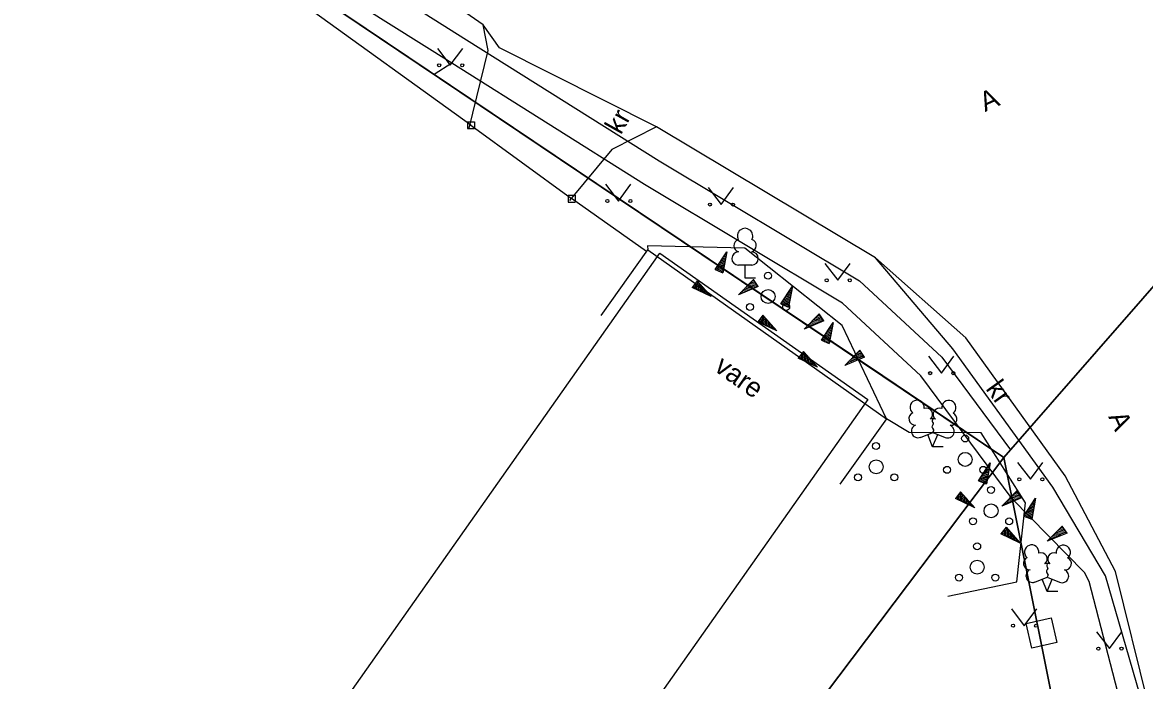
# Model space of a CAD drawing. Extents: x 554947 to 555436, y 6564938 to 6565792.
# Drawn here: x 555307.9 to 555348.19, y 6565504.44 to 6565528.08 of the extents above; entities that cross this region are included whole.
import ezdxf

# ---------------------------------------------------------------- set-up
doc = ezdxf.new("R2010")
doc.units = 0
for name, color, linetype in [('AED', 7, 'Continuous'), ('HALJASTUS', 7, 'Continuous'), ('HOONE', 7, 'Continuous'), ('Hoone Vare', 7, 'Continuous'), ('KASUTUSALA', 7, 'Continuous'), ('PIIR', 7, 'Continuous'), ('PR_SIDE', 7, 'Continuous'), ('PUU', 7, 'Continuous'), ('RELJEEF', 7, 'Continuous'), ('TEE', 7, 'Continuous')]:
    doc.layers.add(name, color=color, linetype=linetype)

msp = doc.modelspace()

# ---------------------------------------------------------------- linework, layer by layer
at = {"layer": 'AED'}
for p, q in [((555323.878, 6565524.515), (555323.878, 6565524.265)), ((555323.878, 6565524.515), (555324.128, 6565524.515)), ((555323.878, 6565524.265), (555324.128, 6565524.265)), ((555324.003, 6565524.39), (555327.619, 6565521.751)), ((555324.128, 6565524.515), (555324.128, 6565524.265)), ((555327.494, 6565521.876), (555327.494, 6565521.626)), ((555327.494, 6565521.876), (555327.744, 6565521.876)), ((555327.744, 6565521.876), (555327.744, 6565521.626)), ((555327.494, 6565521.626), (555327.744, 6565521.626)), ((555330.309, 6565519.858), (555327.619, 6565521.751))]:
    msp.add_line(p, q, dxfattribs=at)
msp.add_lwpolyline([(555324.003, 6565524.39), (555318.054, 6565528.671), (555308.195, 6565535.788)], dxfattribs=at)
msp.add_lwpolyline([(555344.829, 6565506.702), (555345.035, 6565505.809), (555344.14, 6565505.602), (555343.934, 6565506.496)], close=True, dxfattribs=at)
at = {"layer": 'HALJASTUS'}
for p, q in [((555322.798, 6565527.146), (555323.262, 6565526.539)), ((555323.262, 6565526.539), (555323.707, 6565527.146)), ((555328.838, 6565522.273), (555329.302, 6565521.666)), ((555329.302, 6565521.666), (555329.747, 6565522.273)), ((555332.519, 6565522.146), (555332.983, 6565521.539)), ((555332.983, 6565521.539), (555333.428, 6565522.146)), ((555336.713, 6565519.424), (555337.177, 6565518.818)), ((555337.177, 6565518.818), (555337.622, 6565519.424)), ((555340.429, 6565516.091), (555340.892, 6565515.484)), ((555340.892, 6565515.484), (555341.338, 6565516.091)), ((555343.628, 6565512.278), (555344.091, 6565511.672)), ((555344.091, 6565511.672), (555344.537, 6565512.278)), ((555343.405, 6565507.019), (555343.868, 6565506.412)), ((555343.868, 6565506.412), (555344.314, 6565507.019)), ((555346.467, 6565506.198), (555346.931, 6565505.591)), ((555346.931, 6565505.591), (555347.376, 6565506.198))]:
    msp.add_line(p, q, dxfattribs=at)
msp.add_lwpolyline([(555341.125, 6565507.476), (555343.606, 6565507.989), (555343.913, 6565510.824), (555342.324, 6565513.336), (555339.74, 6565513.358), (555338.917, 6565513.849)], dxfattribs=at)
for centre in [(555322.861, 6565526.539), (555323.69, 6565526.539), (555328.9, 6565521.666), (555329.729, 6565521.666), (555332.582, 6565521.539), (555333.411, 6565521.539), (555336.776, 6565518.818), (555337.604, 6565518.818), (555340.491, 6565515.484), (555341.32, 6565515.484), (555343.69, 6565511.672), (555344.519, 6565511.672), (555343.467, 6565506.412), (555344.296, 6565506.412), (555346.53, 6565505.591), (555347.359, 6565505.591)]:
    msp.add_circle(centre, 0.055, dxfattribs=at)
at = {"layer": 'HOONE'}
msp.add_lwpolyline([(555328.683, 6565517.559), (555330.348, 6565519.912), (555338.917, 6565513.849), (555337.251, 6565511.495)], dxfattribs=at)
at = {"layer": 'Hoone Vare'}
msp.add_lwpolyline([(555316.008, 6565482.956), (555308.549, 6565488.207), (555330.789, 6565519.787), (555338.249, 6565514.537)], close=True, dxfattribs=at)
at = {"layer": 'KASUTUSALA'}
msp.add_lwpolyline([(555304.515, 6565541.003), (555310.279, 6565536.49), (555319.603, 6565530.14), (555323.849, 6565527.459), (555330.764, 6565523.11), (555337.948, 6565518.804), (555340.906, 6565516.057), (555343.377, 6565512.73), (555343.14, 6565512.46), (555338.794, 6565515.382), (555330.79, 6565520.761), (555305.197, 6565537.964)], dxfattribs=at)
at = {"layer": 'PIIR'}
for points in [[(555393.069, 6565560.972), (555353.12, 6565523.87), (555343.14, 6565512.46), (555302.6, 6565539.71), (555242.37, 6565583.94), (555179.42, 6565586.32), (555138.98, 6565580.6), (555121.18, 6565602.26), (555116.17, 6565610.5), (555109.96, 6565624.83), (555093.56, 6565628.47), (555079.04, 6565618.4), (555074.13, 6565607.82), (555075.34, 6565593.24), (555091.74, 6565551.94), (555171.91, 6565394.64), (555191.35, 6565341.19), (555195.08, 6565294.61), (555195.28, 6565271.63), (555191.64, 6565237.48)], [(555393.069, 6565443.872), (555367.06, 6565449.68), (555351.96, 6565468.55), (555343.14, 6565512.46), (555353.12, 6565523.87), (555358.8, 6565482.45), (555368.05, 6565461.11), (555393.069, 6565454.923)]]:
    msp.add_lwpolyline(points, dxfattribs=at)
for points in [[(555153.01, 6565448.47), (555161.15, 6565451.45), (555173.66, 6565456.03), (555207.29, 6565506.14), (555287.77, 6565518.56), (555302.6, 6565539.71), (555343.14, 6565512.46), (555319.44, 6565481.04), (555323.07, 6565461.26), (555312.9, 6565433.84), (555316.84, 6565372.52), (555318.72, 6565342.57), (555320.51, 6565314.61), (555303.13, 6565302.54), (555208.78, 6565303.3), (555205.15, 6565297.11), (555200.72, 6565310.3), (555206.9, 6565339.44), (555221.23, 6565376.06), (555216.83, 6565392.35), (555207.22, 6565406.57)], [(555319.44, 6565481.04), (555343.14, 6565512.46), (555351.96, 6565468.55), (555367.06, 6565449.68), (555367.76, 6565374.28), (555361.76, 6565374.07), (555316.84, 6565372.52), (555312.9, 6565433.84), (555323.07, 6565461.26)]]:
    msp.add_lwpolyline(points, close=True, dxfattribs=at)
at = {"layer": 'PR_SIDE'}
for points in [[(555393.069, 6565447.47), (555392.755, 6565447.532), (555372.326, 6565450.448), (555366.015, 6565452.342), (555363.26, 6565453.626), (555360.292, 6565456.785), (555356.82, 6565461.856), (555353.746, 6565469.93), (555350.28, 6565487.806), (555348.596, 6565498.754), (555346.199, 6565508), (555346.027, 6565508.326), (555343.44, 6565510.968), (555340.158, 6565515.387), (555337.344, 6565518), (555330.24, 6565522.258), (555323.316, 6565526.613), (555319.055, 6565529.304), (555309.687, 6565535.684), (555303.916, 6565540.202)], [(555323.316, 6565526.613), (555322.686, 6565526.209)]]:
    msp.add_lwpolyline(points, dxfattribs=at)
at = {"layer": 'PUU'}
for p, q in [((555334.085, 6565519.365), (555333.605, 6565519.365)), ((555333.845, 6565518.89), (555333.845, 6565519.365)), ((555334.225, 6565518.89), (555333.845, 6565518.89)), ((555340.14, 6565513.177), (555340.585, 6565513.352)), ((555340.585, 6565513.352), (555341.025, 6565513.172)), ((555340.58, 6565512.842), (555340.405, 6565513.282)), ((555340.58, 6565512.842), (555340.76, 6565513.282)), ((555340.96, 6565512.842), (555340.58, 6565512.842)), ((555344.251, 6565507.981), (555344.696, 6565508.156)), ((555344.691, 6565507.646), (555344.516, 6565508.086)), ((555344.691, 6565507.646), (555344.871, 6565508.086)), ((555344.696, 6565508.156), (555345.136, 6565507.976)), ((555345.071, 6565507.646), (555344.691, 6565507.646))]:
    msp.add_line(p, q, dxfattribs=at)
for points in [[(555340.585, 6565513.847), (555340.565, 6565513.772), (555340.565, 6565513.752), (555340.575, 6565513.722), (555340.595, 6565513.687), (555340.6, 6565513.667), (555340.585, 6565513.632), (555340.56, 6565513.582), (555340.555, 6565513.557), (555340.56, 6565513.542), (555340.57, 6565513.512), (555340.605, 6565513.452), (555340.61, 6565513.432), (555340.605, 6565513.412), (555340.59, 6565513.377), (555340.585, 6565513.352)], [(555344.696, 6565508.651), (555344.676, 6565508.576), (555344.676, 6565508.556), (555344.686, 6565508.526), (555344.706, 6565508.491), (555344.711, 6565508.471), (555344.696, 6565508.436), (555344.671, 6565508.386), (555344.666, 6565508.361), (555344.671, 6565508.346), (555344.681, 6565508.316), (555344.716, 6565508.256), (555344.721, 6565508.236), (555344.716, 6565508.216), (555344.701, 6565508.181), (555344.696, 6565508.156)]]:
    msp.add_lwpolyline(points, dxfattribs=at)
for centre, radius in [((555334.67, 6565518.984), 0.125), ((555334.67, 6565518.234), 0.25), ((555334.02, 6565517.859), 0.125), ((555335.32, 6565517.859), 0.125), ((555338.55, 6565512.867), 0.125), ((555341.746, 6565513.137), 0.125), ((555341.746, 6565512.387), 0.25), ((555338.55, 6565512.117), 0.25), ((555341.096, 6565512.012), 0.125), ((555342.396, 6565512.012), 0.125), ((555337.9, 6565511.742), 0.125), ((555339.2, 6565511.742), 0.125), ((555342.676, 6565511.289), 0.125), ((555342.676, 6565510.539), 0.25), ((555342.026, 6565510.164), 0.125), ((555343.326, 6565510.164), 0.125), ((555342.177, 6565509.265), 0.125), ((555342.177, 6565508.515), 0.25), ((555341.527, 6565508.14), 0.125), ((555342.827, 6565508.14), 0.125)]:
    msp.add_circle(centre, radius, dxfattribs=at)
for centre, radius, start, end in [((555333.845, 6565520.41), 0.277, 332.5799, 207.4201), ((555333.675, 6565520.062), 0.233, 109.0217, 253.1415), ((555334.015, 6565520.062), 0.233, 286.8508, 70.9859), ((555333.607, 6565519.602), 0.238, 90.0016, 269.3953), ((555334.082, 6565519.602), 0.238, 270.6047, 89.9984), ((555340.023, 6565514.256), 0.256, 111.5027, 232.5173), ((555340.023, 6565514.256), 0.256, 350.4856, 111.5002), ((555340.358, 6565514.006), 0.224, 308.5041, 111.5725), ((555340.821, 6565514.001), 0.225, 67.7016, 230.5126), ((555341.159, 6565514.248), 0.256, 67.6168, 188.6314), ((555341.159, 6565514.248), 0.256, 306.5997, 67.6143), ((555339.949, 6565513.845), 0.224, 111.4304, 274.4987), ((555340.584, 6565513.609), 0.237, 66.7655, 111.5015), ((555341.227, 6565513.835), 0.224, 264.6183, 67.6866), ((555340.054, 6565513.401), 0.237, 111.5014, 291.5004), ((555341.115, 6565513.392), 0.237, 247.6166, 67.6155), ((555344.134, 6565509.06), 0.256, 111.5027, 232.5173), ((555344.134, 6565509.06), 0.256, 350.4856, 111.5002), ((555345.27, 6565509.051), 0.256, 67.6168, 188.6314), ((555345.27, 6565509.051), 0.256, 306.5997, 67.6143), ((555344.468, 6565508.81), 0.224, 308.5041, 111.5725), ((555344.932, 6565508.805), 0.225, 67.7016, 230.5126), ((555344.06, 6565508.649), 0.224, 111.4304, 274.4987), ((555344.695, 6565508.413), 0.237, 66.7655, 111.5015), ((555345.337, 6565508.639), 0.224, 264.6183, 67.6866), ((555344.165, 6565508.204), 0.237, 111.5014, 291.5004), ((555345.226, 6565508.196), 0.237, 247.6166, 67.6155)]:
    msp.add_arc(centre, radius, start, end, dxfattribs=at)
at = {"layer": 'RELJEEF'}
for p, q in [((555332.769, 6565519.206), (555333.189, 6565519.846)), ((555333.189, 6565519.846), (555333.049, 6565519.091)), ((555333.164, 6565519.806), (555333.184, 6565519.816)), ((555332.819, 6565519.281), (555333.104, 6565519.401)), ((555332.869, 6565519.356), (555333.119, 6565519.461)), ((555332.919, 6565519.431), (555333.044, 6565519.486)), ((555332.969, 6565519.506), (555333.139, 6565519.581)), ((555333.019, 6565519.581), (555333.149, 6565519.641)), ((555333.044, 6565519.486), (555333.129, 6565519.521)), ((555333.064, 6565519.656), (555333.164, 6565519.696)), ((555333.114, 6565519.731), (555333.174, 6565519.756)), ((555332.769, 6565519.206), (555333.094, 6565519.346)), ((555332.769, 6565519.206), (555333.049, 6565519.091)), ((555332.769, 6565519.206), (555332.769, 6565519.206)), ((555332.834, 6565519.181), (555333.084, 6565519.286)), ((555332.899, 6565519.151), (555333.074, 6565519.226)), ((555332.969, 6565519.126), (555333.064, 6565519.166)), ((555333.034, 6565519.101), (555333.049, 6565519.106)), ((555332.127, 6565518.805), (555331.942, 6565518.565)), ((555332.632, 6565518.235), (555331.942, 6565518.565)), ((555331.952, 6565518.58), (555331.957, 6565518.56)), ((555331.997, 6565518.635), (555332.012, 6565518.535)), ((555332.042, 6565518.695), (555332.067, 6565518.51)), ((555332.082, 6565518.75), (555332.117, 6565518.48)), ((555332.127, 6565518.805), (555332.632, 6565518.235)), ((555332.127, 6565518.805), (555332.172, 6565518.455)), ((555332.127, 6565518.805), (555332.127, 6565518.805)), ((555332.187, 6565518.74), (555332.227, 6565518.43)), ((555332.247, 6565518.67), (555332.282, 6565518.405)), ((555332.307, 6565518.605), (555332.322, 6565518.465)), ((555333.607, 6565518.3), (555334.147, 6565518.845)), ((555334.317, 6565518.595), (555333.607, 6565518.3)), ((555334.147, 6565518.525), (555333.882, 6565518.575)), ((555334.232, 6565518.56), (555333.927, 6565518.62)), ((555334.317, 6565518.595), (555333.967, 6565518.66)), ((555334.277, 6565518.65), (555334.012, 6565518.705)), ((555334.237, 6565518.71), (555334.052, 6565518.745)), ((555334.197, 6565518.77), (555334.097, 6565518.79)), ((555334.157, 6565518.83), (555334.137, 6565518.83)), ((555334.317, 6565518.595), (555334.147, 6565518.845)), ((555334.317, 6565518.595), (555334.317, 6565518.595)), ((555335.127, 6565517.97), (555335.547, 6565518.61)), ((555335.547, 6565518.61), (555335.407, 6565517.855)), ((555335.522, 6565518.57), (555335.542, 6565518.58)), ((555332.322, 6565518.465), (555332.337, 6565518.375)), ((555332.362, 6565518.535), (555332.392, 6565518.35)), ((555332.422, 6565518.47), (555332.442, 6565518.325)), ((555332.482, 6565518.4), (555332.497, 6565518.3)), ((555332.542, 6565518.335), (555332.552, 6565518.27)), ((555332.602, 6565518.265), (555332.607, 6565518.245)), ((555333.647, 6565518.315), (555333.632, 6565518.32)), ((555333.732, 6565518.35), (555333.672, 6565518.365)), ((555333.817, 6565518.385), (555333.712, 6565518.405)), ((555333.897, 6565518.42), (555333.757, 6565518.45)), ((555333.982, 6565518.455), (555333.797, 6565518.49)), ((555333.932, 6565518.515), (555333.842, 6565518.535)), ((555334.067, 6565518.49), (555333.932, 6565518.515)), ((555335.177, 6565518.045), (555335.462, 6565518.165)), ((555335.227, 6565518.12), (555335.477, 6565518.225)), ((555335.277, 6565518.195), (555335.402, 6565518.25)), ((555335.327, 6565518.27), (555335.497, 6565518.345)), ((555335.377, 6565518.345), (555335.507, 6565518.405)), ((555335.402, 6565518.25), (555335.487, 6565518.285)), ((555335.422, 6565518.42), (555335.522, 6565518.46)), ((555335.472, 6565518.495), (555335.532, 6565518.52)), ((555335.127, 6565517.97), (555335.452, 6565518.11)), ((555335.127, 6565517.97), (555335.407, 6565517.855)), ((555335.127, 6565517.97), (555335.127, 6565517.97)), ((555335.192, 6565517.945), (555335.442, 6565518.05)), ((555335.257, 6565517.915), (555335.432, 6565517.99)), ((555335.327, 6565517.89), (555335.422, 6565517.93)), ((555335.392, 6565517.865), (555335.407, 6565517.87)), ((555334.486, 6565517.569), (555334.301, 6565517.329)), ((555334.311, 6565517.344), (555334.316, 6565517.324)), ((555334.356, 6565517.399), (555334.371, 6565517.299)), ((555334.401, 6565517.459), (555334.426, 6565517.274)), ((555334.441, 6565517.514), (555334.476, 6565517.244)), ((555334.486, 6565517.569), (555334.991, 6565516.999)), ((555334.486, 6565517.569), (555334.531, 6565517.219)), ((555334.486, 6565517.569), (555334.486, 6565517.569)), ((555334.546, 6565517.504), (555334.586, 6565517.194)), ((555334.606, 6565517.434), (555334.641, 6565517.169)), ((555334.666, 6565517.369), (555334.681, 6565517.229)), ((555335.965, 6565517.064), (555336.505, 6565517.609)), ((555336.675, 6565517.359), (555335.965, 6565517.064)), ((555336.59, 6565517.324), (555336.285, 6565517.384)), ((555336.675, 6565517.359), (555336.325, 6565517.424)), ((555336.635, 6565517.414), (555336.37, 6565517.469)), ((555336.595, 6565517.474), (555336.41, 6565517.509)), ((555336.555, 6565517.534), (555336.455, 6565517.554)), ((555336.515, 6565517.594), (555336.495, 6565517.594)), ((555336.675, 6565517.359), (555336.505, 6565517.609)), ((555336.675, 6565517.359), (555336.675, 6565517.359)), ((555334.991, 6565516.999), (555334.301, 6565517.329)), ((555334.681, 6565517.229), (555334.696, 6565517.139)), ((555334.721, 6565517.299), (555334.751, 6565517.114)), ((555334.781, 6565517.234), (555334.801, 6565517.089)), ((555334.841, 6565517.164), (555334.856, 6565517.064)), ((555334.901, 6565517.099), (555334.911, 6565517.034)), ((555334.961, 6565517.029), (555334.966, 6565517.009)), ((555336.005, 6565517.079), (555335.99, 6565517.084)), ((555336.09, 6565517.114), (555336.03, 6565517.129)), ((555336.175, 6565517.149), (555336.07, 6565517.169)), ((555336.255, 6565517.184), (555336.115, 6565517.214)), ((555336.34, 6565517.219), (555336.155, 6565517.254)), ((555336.29, 6565517.279), (555336.2, 6565517.299)), ((555336.505, 6565517.289), (555336.24, 6565517.339)), ((555336.425, 6565517.254), (555336.29, 6565517.279)), ((555336.584, 6565516.665), (555337.004, 6565517.305)), ((555336.734, 6565516.89), (555336.859, 6565516.945)), ((555336.784, 6565516.965), (555336.954, 6565517.04)), ((555336.834, 6565517.04), (555336.964, 6565517.1)), ((555336.859, 6565516.945), (555336.944, 6565516.98)), ((555337.004, 6565517.305), (555336.864, 6565516.55)), ((555336.879, 6565517.115), (555336.979, 6565517.155)), ((555336.929, 6565517.19), (555336.989, 6565517.215)), ((555336.979, 6565517.265), (555336.999, 6565517.275)), ((555336.584, 6565516.665), (555336.909, 6565516.805)), ((555336.584, 6565516.665), (555336.864, 6565516.55)), ((555336.584, 6565516.665), (555336.584, 6565516.665)), ((555336.634, 6565516.74), (555336.919, 6565516.86)), ((555336.649, 6565516.64), (555336.899, 6565516.745)), ((555336.684, 6565516.815), (555336.934, 6565516.92)), ((555336.714, 6565516.61), (555336.889, 6565516.685)), ((555336.784, 6565516.585), (555336.879, 6565516.625)), ((555336.849, 6565516.56), (555336.864, 6565516.565)), ((555335.942, 6565516.264), (555335.757, 6565516.024)), ((555335.857, 6565516.154), (555335.882, 6565515.969)), ((555335.897, 6565516.209), (555335.932, 6565515.939)), ((555335.942, 6565516.264), (555336.447, 6565515.694)), ((555335.942, 6565516.264), (555335.987, 6565515.914)), ((555335.942, 6565516.264), (555335.942, 6565516.264)), ((555336.002, 6565516.199), (555336.042, 6565515.889)), ((555337.421, 6565515.759), (555337.961, 6565516.304)), ((555338.091, 6565516.109), (555337.826, 6565516.164)), ((555338.051, 6565516.169), (555337.866, 6565516.204)), ((555338.011, 6565516.229), (555337.911, 6565516.249)), ((555337.971, 6565516.289), (555337.951, 6565516.289)), ((555338.131, 6565516.054), (555337.961, 6565516.304)), ((555336.447, 6565515.694), (555335.757, 6565516.024)), ((555335.767, 6565516.039), (555335.772, 6565516.019)), ((555335.812, 6565516.094), (555335.827, 6565515.994)), ((555336.062, 6565516.129), (555336.097, 6565515.864)), ((555336.122, 6565516.064), (555336.137, 6565515.924)), ((555336.137, 6565515.924), (555336.152, 6565515.834)), ((555336.177, 6565515.994), (555336.207, 6565515.809)), ((555336.237, 6565515.929), (555336.257, 6565515.784)), ((555336.297, 6565515.859), (555336.312, 6565515.759)), ((555336.357, 6565515.794), (555336.367, 6565515.729)), ((555338.131, 6565516.054), (555337.421, 6565515.759)), ((555337.461, 6565515.774), (555337.446, 6565515.779)), ((555337.546, 6565515.809), (555337.486, 6565515.824)), ((555337.631, 6565515.844), (555337.526, 6565515.864)), ((555337.711, 6565515.879), (555337.571, 6565515.909)), ((555337.796, 6565515.914), (555337.611, 6565515.949)), ((555337.746, 6565515.974), (555337.656, 6565515.994)), ((555337.961, 6565515.984), (555337.696, 6565516.034)), ((555338.046, 6565516.019), (555337.741, 6565516.079)), ((555337.881, 6565515.949), (555337.746, 6565515.974)), ((555338.131, 6565516.054), (555337.781, 6565516.119)), ((555338.131, 6565516.054), (555338.131, 6565516.054)), ((555336.417, 6565515.724), (555336.422, 6565515.704)), ((555342.227, 6565511.618), (555342.647, 6565512.258)), ((555342.647, 6565512.258), (555342.507, 6565511.503)), ((555342.522, 6565512.068), (555342.622, 6565512.108)), ((555342.572, 6565512.143), (555342.632, 6565512.168)), ((555342.622, 6565512.218), (555342.642, 6565512.228)), ((555342.227, 6565511.618), (555342.552, 6565511.758)), ((555342.277, 6565511.693), (555342.562, 6565511.813)), ((555342.327, 6565511.768), (555342.577, 6565511.873)), ((555342.377, 6565511.843), (555342.502, 6565511.898)), ((555342.427, 6565511.918), (555342.597, 6565511.993)), ((555342.477, 6565511.993), (555342.607, 6565512.053)), ((555342.502, 6565511.898), (555342.587, 6565511.933)), ((555342.227, 6565511.618), (555342.507, 6565511.503)), ((555342.227, 6565511.618), (555342.227, 6565511.618)), ((555342.292, 6565511.593), (555342.542, 6565511.698)), ((555342.357, 6565511.563), (555342.532, 6565511.638)), ((555342.427, 6565511.538), (555342.522, 6565511.578)), ((555342.492, 6565511.513), (555342.507, 6565511.518)), ((555341.585, 6565511.217), (555341.4, 6565510.977)), ((555342.09, 6565510.647), (555341.4, 6565510.977)), ((555341.41, 6565510.992), (555341.415, 6565510.972)), ((555341.455, 6565511.047), (555341.47, 6565510.947)), ((555341.5, 6565511.107), (555341.525, 6565510.922)), ((555341.54, 6565511.162), (555341.575, 6565510.892)), ((555341.585, 6565511.217), (555342.09, 6565510.647)), ((555341.585, 6565511.217), (555341.63, 6565510.867)), ((555341.585, 6565511.217), (555341.585, 6565511.217)), ((555341.645, 6565511.152), (555341.685, 6565510.842)), ((555341.705, 6565511.082), (555341.74, 6565510.817)), ((555341.765, 6565511.017), (555341.78, 6565510.877)), ((555341.82, 6565510.947), (555341.85, 6565510.762)), ((555343.065, 6565510.712), (555343.605, 6565511.257)), ((555343.775, 6565511.007), (555343.065, 6565510.712)), ((555343.44, 6565510.867), (555343.255, 6565510.902)), ((555343.39, 6565510.927), (555343.3, 6565510.947)), ((555343.605, 6565510.937), (555343.34, 6565510.987)), ((555343.69, 6565510.972), (555343.385, 6565511.032)), ((555343.525, 6565510.902), (555343.39, 6565510.927)), ((555343.775, 6565511.007), (555343.425, 6565511.072)), ((555343.735, 6565511.062), (555343.47, 6565511.117)), ((555343.695, 6565511.122), (555343.51, 6565511.157)), ((555343.655, 6565511.182), (555343.555, 6565511.202)), ((555343.615, 6565511.242), (555343.595, 6565511.242)), ((555343.775, 6565511.007), (555343.605, 6565511.257)), ((555343.775, 6565511.007), (555343.775, 6565511.007)), ((555343.857, 6565510.352), (555344.277, 6565510.992)), ((555344.277, 6565510.992), (555344.137, 6565510.237)), ((555344.202, 6565510.877), (555344.262, 6565510.902)), ((555344.252, 6565510.952), (555344.272, 6565510.962)), ((555341.78, 6565510.877), (555341.795, 6565510.787)), ((555341.88, 6565510.882), (555341.9, 6565510.737)), ((555341.94, 6565510.812), (555341.955, 6565510.712)), ((555342, 6565510.747), (555342.01, 6565510.682)), ((555342.06, 6565510.677), (555342.065, 6565510.657)), ((555343.105, 6565510.727), (555343.09, 6565510.732)), ((555343.19, 6565510.762), (555343.13, 6565510.777)), ((555343.275, 6565510.797), (555343.17, 6565510.817)), ((555343.355, 6565510.832), (555343.215, 6565510.862)), ((555343.857, 6565510.352), (555344.182, 6565510.492)), ((555343.907, 6565510.427), (555344.192, 6565510.547)), ((555343.957, 6565510.502), (555344.207, 6565510.607)), ((555344.007, 6565510.577), (555344.132, 6565510.632)), ((555344.057, 6565510.652), (555344.227, 6565510.727)), ((555344.107, 6565510.727), (555344.237, 6565510.787)), ((555344.132, 6565510.632), (555344.217, 6565510.667)), ((555344.152, 6565510.802), (555344.252, 6565510.842)), ((555343.857, 6565510.352), (555344.137, 6565510.237)), ((555343.857, 6565510.352), (555343.857, 6565510.352)), ((555343.922, 6565510.327), (555344.172, 6565510.432)), ((555343.987, 6565510.297), (555344.162, 6565510.372)), ((555344.057, 6565510.272), (555344.152, 6565510.312)), ((555344.122, 6565510.247), (555344.137, 6565510.252)), ((555343.216, 6565509.951), (555343.031, 6565509.711)), ((555343.721, 6565509.381), (555343.031, 6565509.711)), ((555343.041, 6565509.726), (555343.046, 6565509.706)), ((555343.086, 6565509.781), (555343.101, 6565509.681)), ((555343.131, 6565509.841), (555343.156, 6565509.656)), ((555343.171, 6565509.896), (555343.206, 6565509.626)), ((555343.216, 6565509.951), (555343.721, 6565509.381)), ((555343.216, 6565509.951), (555343.261, 6565509.601)), ((555343.216, 6565509.951), (555343.216, 6565509.951)), ((555343.276, 6565509.886), (555343.316, 6565509.576)), ((555343.336, 6565509.816), (555343.371, 6565509.551)), ((555343.396, 6565509.751), (555343.411, 6565509.611)), ((555344.695, 6565509.446), (555345.235, 6565509.991)), ((555345.405, 6565509.741), (555344.695, 6565509.446)), ((555345.235, 6565509.671), (555344.97, 6565509.721)), ((555345.32, 6565509.706), (555345.015, 6565509.766)), ((555345.405, 6565509.741), (555345.055, 6565509.806)), ((555345.365, 6565509.796), (555345.1, 6565509.851)), ((555345.325, 6565509.856), (555345.14, 6565509.891)), ((555345.285, 6565509.916), (555345.185, 6565509.936)), ((555345.245, 6565509.976), (555345.225, 6565509.976)), ((555345.405, 6565509.741), (555345.235, 6565509.991)), ((555345.405, 6565509.741), (555345.405, 6565509.741)), ((555343.411, 6565509.611), (555343.426, 6565509.521)), ((555343.451, 6565509.681), (555343.481, 6565509.496)), ((555343.511, 6565509.616), (555343.531, 6565509.471)), ((555343.571, 6565509.546), (555343.586, 6565509.446)), ((555343.631, 6565509.481), (555343.641, 6565509.416)), ((555343.691, 6565509.411), (555343.696, 6565509.391)), ((555344.735, 6565509.461), (555344.72, 6565509.466)), ((555344.82, 6565509.496), (555344.76, 6565509.511)), ((555344.905, 6565509.531), (555344.8, 6565509.551)), ((555344.985, 6565509.566), (555344.845, 6565509.596)), ((555345.07, 6565509.601), (555344.885, 6565509.636)), ((555345.02, 6565509.661), (555344.93, 6565509.681)), ((555345.155, 6565509.636), (555345.02, 6565509.661))]:
    msp.add_line(p, q, dxfattribs=at)
msp.add_lwpolyline([(555338.917, 6565513.849), (555337.332, 6565517.196), (555333.839, 6565519.972), (555330.337, 6565520.057), (555330.348, 6565519.912)], dxfattribs=at)
at = {"layer": 'TEE'}
for points in [[(555393.069, 6565448.493), (555392.904, 6565448.521), (555377.792, 6565450.52), (555372.547, 6565451.424), (555369.187, 6565452.37), (555366.443, 6565453.255), (555364.23, 6565454.662), (555361.13, 6565458.083), (555357.411, 6565463.749), (555354.693, 6565470.258), (555353.748, 6565473.64), (555352.733, 6565478.362), (555351.267, 6565487.961), (555349.516, 6565498.784), (555347.141, 6565508.358), (555345.332, 6565511.802), (555341.773, 6565516.752), (555338.53, 6565519.62), (555330.669, 6565524.333), (555325.029, 6565527.171), (555324.447, 6565527.997), (555320.204, 6565530.941)], [(555323.943, 6565524.277), (555324.617, 6565527.067), (555324.447, 6565527.997)], [(555330.669, 6565524.333), (555329.063, 6565523.521), (555327.542, 6565521.69)], [(555349.516, 6565498.784), (555346.789, 6565508.206), (555344.895, 6565511.389), (555341.304, 6565516.362), (555338.53, 6565519.62)]]:
    msp.add_lwpolyline(points, dxfattribs=at)

# ---------------------------------------------------------------- texts
at = {"layer": 'HOONE'}
msp.add_text('vare', height=0.7, rotation=324.7128, dxfattribs=at).set_placement((555332.696, 6565515.596))
at = {"layer": 'TEE'}
for s, rotation, p in [('A', 24.2113, (555342.463, 6565524.862)), ('kr', 60.7642, (555329.386, 6565524.02)), ('kr', 305.7829, (555342.463, 6565514.921)), ('A', 294.6382, (555346.878, 6565513.921))]:
    msp.add_text(s, height=0.7, rotation=rotation, dxfattribs=at).set_placement(p)

doc.saveas('drawing.dxf')
